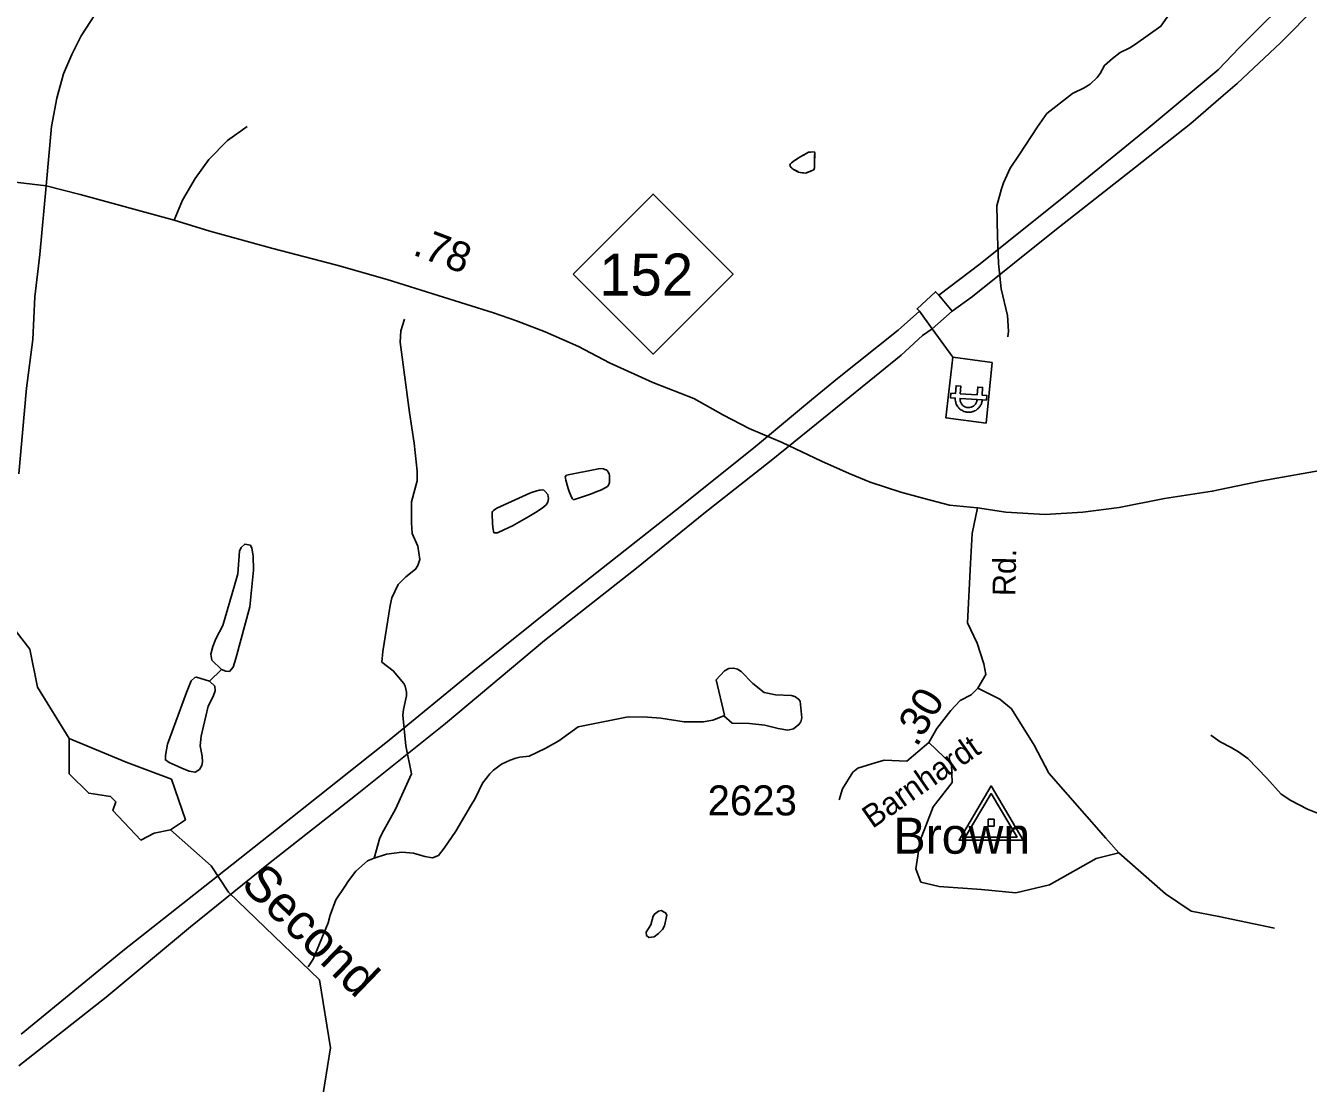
# Model space of a CAD drawing. Extents: x 1473865 to 1648260, y 639067 to 773536.
# Drawn here: x 1559198 to 1564537, y 655168 to 659571 of the extents above; entities that cross this region are included whole.
import ezdxf

# ---------------------------------------------------------------- set-up
doc = ezdxf.new("R2010")
doc.units = 0
for name, color, linetype in [('Exist Hydrographic Creek Single Shore', 7, 'Continuous'), ('Exist Hydrographic Creek Single Shore Label', 7, 'Continuous'), ('Exist Hydrographic Misc Water Feature', 7, 'Continuous'), ('Exist Road Non-System Type 51', 7, 'Continuous'), ('Exist Road Primary NC Attributed', 7, 'Continuous'), ('Exist Road Primary NC Service Mileage Hundredths English Label', 7, 'Continuous'), ('Exist Road Primary NC Shield CELL', 7, 'Continuous'), ('Exist Road Primary NC Shield Number Label', 7, 'Continuous'), ('Exist Road Secondary Mileage Hundredths English Label', 7, 'Continuous'), ('Exist Road Secondary Type 51 Attributed', 7, 'Continuous'), ('Exist Road Secondary Type 51 Label', 7, 'Continuous'), ('Exist Road Secondary Type 51 Number Label', 7, 'Continuous'), ('Exist Survey Geodetic Marker CELL', 7, 'Continuous'), ('Exist Survey Geodetic Marker Label', 7, 'Continuous'), ('Exist Utilities Electrical Power Substation CELL', 7, 'Continuous'), ('Exist Utilities Electrical Transmission Line', 7, 'Continuous')]:
    doc.layers.add(name, color=color, linetype=linetype)

msp = doc.modelspace()

# ---------------------------------------------------------------- linework, layer by layer
at = {"layer": 'Exist Hydrographic Creek Single Shore'}
msp.add_lwpolyline([(1560429.2, 655083), (1560466.2, 655315.3), (1560420.2, 655598.5), (1560042.2, 655963.9), (1559969.2, 656073.7), (1559800.9, 656222.4), (1559862.6, 656264.7), (1559804.2, 656433.7), (1559616.2, 656504.2), (1559378.7, 656602.7), (1559246.3, 656817), (1559215.2, 656975.2), (1559010.3, 657238.6)], dxfattribs=at)
at = {"layer": 'Exist Hydrographic Misc Water Feature'}
msp.add_line((1559962.9, 656841.7), (1560013.1, 656890.8), dxfattribs=at)
for points in [[(1563959.4, 659619.6), (1563922.8, 659568.1), (1563817.9, 659493.3), (1563793.7, 659477.6), (1563753.5, 659458.1), (1563721.2, 659434.4), (1563688.8, 659404.8), (1563670.5, 659371), (1563658.3, 659355.1), (1563628, 659327.5), (1563603.8, 659311.8), (1563555.6, 659288.3), (1563448.9, 659204.6), (1563410, 659150), (1563332.7, 659032.9), (1563296, 658977.3), (1563267.4, 658915.6), (1563259.1, 658891.8), (1563240.3, 658819.9), (1563243.3, 658694.3), (1563247.6, 658579.9), (1563258.4, 658475.7), (1563285.2, 658363.4), (1563288.5, 658299.4), (1563286.2, 658275.4)], [(1562478.7, 658971), (1562470.9, 658967.5), (1562467.8, 658965.8), (1562463.3, 658963.7), (1562457.6, 658962.6), (1562453.6, 658960.8), (1562448.1, 658958.1), (1562445.1, 658956.4), (1562435.6, 658957.7), (1562430.6, 658957.2), (1562421.9, 658959.3), (1562414.4, 658960.8), (1562411.3, 658962.8), (1562406.4, 658966.8), (1562397.9, 658969.7), (1562393.8, 658971.9), (1562387.2, 658976.8), (1562384, 658979.7), (1562379.5, 658985.2), (1562379, 658989.5), (1562380, 658994.6), (1562385.6, 658999.7), (1562391.3, 659003.8), (1562397.8, 659009.3), (1562403.2, 659011.6), (1562409, 659016.2), (1562413.2, 659019.4), (1562417.2, 659021.9), (1562421.6, 659024.2), (1562427.6, 659027.2), (1562431.2, 659029.4), (1562438.7, 659031.9), (1562442.7, 659036.2), (1562455.5, 659043.5), (1562459.7, 659043.6), (1562464.8, 659044.2), (1562473.3, 659045.1), (1562481.6, 659044), (1562482.1, 659040.6), (1562480.9, 659029.9), (1562481.2, 659023.4), (1562481, 659012.3), (1562481, 659007.4), (1562481.1, 659001.1), (1562481.8, 658995.7), (1562481.7, 658989.9), (1562481.5, 658984.4), (1562481.4, 658979.3), (1562478.7, 658971)], [(1562478.7, 658971), (1562470.9, 658967.5), (1562445.1, 658956.4), (1562430.6, 658957.2), (1562414.4, 658960.8), (1562393.8, 658971.9), (1562387.2, 658976.8), (1562384, 658979.7), (1562379.5, 658985.2), (1562379, 658989.5), (1562380, 658994.6), (1562385.6, 658999.7), (1562397.8, 659009.3), (1562413.2, 659019.4), (1562417.2, 659021.9), (1562455.5, 659043.5), (1562473.3, 659045.1), (1562481.6, 659044), (1562482.1, 659040.6), (1562481.8, 658995.7), (1562481.7, 658989.9), (1562481.4, 658979.3), (1562478.7, 658971)], [(1560648.1, 656105.7), (1560672.1, 656189.6), (1560688.5, 656221.4), (1560737.5, 656308.9), (1560803.1, 656456.1), (1560780.4, 656572.4), (1560767.9, 656700.6), (1560770.1, 656724.5), (1560782.7, 656780.4), (1560782.9, 656796.4), (1560777.2, 656820.5), (1560771.3, 656832.5), (1560727.9, 656885), (1560680.2, 656921.6), (1560683.7, 656965.3), (1560714.9, 657157.2), (1560721.2, 657189.2), (1560747.9, 657244.8), (1560780.2, 657276.5), (1560820.6, 657308), (1560830.7, 657323.9), (1560839, 657347.8), (1560829.7, 657403.9), (1560806.2, 657456.2), (1560803, 657501.3), (1560803.7, 657588.2), (1560826.6, 657676), (1560827.1, 657715.9), (1560814.4, 657832.1), (1560795.8, 657960.4), (1560757, 658252.8), (1560759.6, 658300.8), (1560774.1, 658348.6)], [(1561477.6, 657597.4), (1561473.4, 657600.8), (1561469.7, 657608.4), (1561460.4, 657630.9), (1561456.3, 657643.3), (1561445.8, 657678.1), (1561444, 657687.6), (1561443.6, 657692.9), (1561449, 657699), (1561581.4, 657726.2), (1561595.7, 657726.5), (1561602.3, 657725.5), (1561608.5, 657723.5), (1561614.6, 657721.5), (1561619.4, 657717.7), (1561622.1, 657712.4), (1561625.8, 657705.2), (1561627.7, 657697.6), (1561628.4, 657682.4), (1561627.4, 657669.5), (1561624.3, 657658.2), (1561619, 657652.1), (1561594.5, 657638.6), (1561583.6, 657634), (1561544.4, 657618.8), (1561527.3, 657613.4), (1561477.6, 657597.4)], [(1561140.3, 657547.5), (1561139.8, 657544.3), (1561139.6, 657526.8), (1561140.5, 657510), (1561141.1, 657499.4), (1561142.3, 657482.2), (1561146.8, 657459.5), (1561161.4, 657459.7), (1561187.8, 657471.4), (1561224.1, 657488.8), (1561291.8, 657527.7), (1561320.5, 657544.5), (1561346.9, 657561.6), (1561364.7, 657576.3), (1561371.3, 657587.2), (1561373.7, 657601.8), (1561371, 657619.3), (1561360.3, 657631.5), (1561355.1, 657636.7), (1561348.7, 657638.6), (1561339.5, 657637.2), (1561335.2, 657636.6), (1561324.9, 657634.5), (1561303.3, 657627.2), (1561296.3, 657624.3), (1561158.6, 657562.3), (1561154.2, 657559.4), (1561144.7, 657551.8), (1561140.3, 657547.5)], [(1560013.1, 656890.8), (1560031.5, 656883.1), (1560045.8, 656882.8), (1560061.8, 656900.8), (1560072.2, 656936.7), (1560130.6, 657152), (1560146.3, 657303.8), (1560144.9, 657363.9), (1560139.3, 657396), (1560133.4, 657408), (1560109.5, 657412.3), (1560095.3, 657398.5), (1560087.1, 657382.5), (1560080.1, 657288.6), (1560067.5, 657240.7), (1560017.7, 657073.3), (1559989.1, 657017.6), (1559976.7, 656985.8), (1559968.4, 656953.9), (1559972.1, 656929.8), (1560013.1, 656890.8)], [(1562103.2, 656698.1), (1562106.4, 656701), (1562072, 656847.4), (1562106.4, 656885), (1562124.5, 656894.8), (1562144.5, 656896.5), (1562160.5, 656892.3), (1562176.4, 656882.1), (1562223.8, 656831.6), (1562271.4, 656795), (1562319.4, 656784.5), (1562383.4, 656781.8), (1562399.3, 656777.6), (1562415.2, 656767.4), (1562421.1, 656759.3), (1562428.4, 656689.2), (1562424.2, 656673.2), (1562416.1, 656661.4), (1562393.8, 656643.6), (1562369.7, 656637.9), (1562329.9, 656644.4), (1562274, 656659), (1562210, 656665.8), (1562138, 656666.6), (1562103.2, 656698.1)], [(1559833.1, 656487.4), (1559795.3, 656503.9), (1559779.4, 656514), (1559779.6, 656532), (1559788.1, 656579.9), (1559866.6, 656795), (1559887.1, 656842.8), (1559901.2, 656856.7), (1559909.2, 656858.6), (1559962.9, 656841.7)], [(1559962.9, 656841.7), (1559984.9, 656821.7), (1559986.6, 656801.7), (1559978.4, 656777.8), (1559957.9, 656738), (1559928.6, 656612.3), (1559924.1, 656572.4), (1559931.7, 656530.3), (1559933.4, 656506.2), (1559931.2, 656490.3), (1559921, 656474.4), (1559902.9, 656462.6), (1559878.9, 656466.9), (1559847.1, 656479.3), (1559833.1, 656487.4)], [(1560648.1, 656105.7), (1560699.4, 656121.3), (1560763.6, 656130.5), (1560811.4, 656126), (1560859.3, 656111.5), (1560891.3, 656107), (1560915.4, 656116.8), (1560939.8, 656146.5), (1560988.6, 656217.9), (1561049.7, 656321.2), (1561068.1, 656353), (1561098.8, 656416.7), (1561129.3, 656456.3), (1561145.5, 656472.1), (1561177.8, 656495.8), (1561214, 656513.4), (1561238.1, 656521), (1561254.1, 656524.9), (1561294.1, 656530.4), (1561360.6, 656561.6), (1561416.9, 656593), (1561497.6, 656652.1), (1561706.1, 656693.7), (1561786.2, 656692.7), (1561842.1, 656688.1), (1561938, 656672.9), (1562018, 656672), (1562058.1, 656679.6), (1562103.2, 656698.1)], [(1564574.8, 656292.2), (1564532.9, 656308.7), (1564463.3, 656345.5), (1564423.5, 656372), (1564364.3, 656438.7), (1564285.1, 656519.6), (1564245.5, 656548.1), (1564215.6, 656566.4), (1564169.9, 656588.9), (1564130.2, 656617.4)], [(1559378.7, 656602.7), (1559378.7, 656456.4), (1559459.9, 656375.2), (1559550.9, 656362.2), (1559573.6, 656339.4), (1559560.6, 656303.7), (1559677.5, 656180.1), (1559732.7, 656209.4), (1559800.9, 656222.4)], [(1560374.1, 655653.1), (1560394.5, 655684.8), (1560456.2, 655836.1), (1560464.5, 655868), (1560489.2, 655931.7), (1560525.8, 655987.3), (1560542.1, 656011.1), (1560572.6, 656050.8), (1560621.1, 656094.2), (1560648.1, 656105.7)], [(1561799.5, 655827.2), (1561809, 655864.4), (1561815.1, 655872.3), (1561831.2, 655884.1), (1561843.3, 655888), (1561861.1, 655877.7), (1561867.1, 655867.7), (1561856.6, 655823.8), (1561848.4, 655807.9), (1561832.2, 655792.1), (1561814.1, 655778.3), (1561792, 655774.6), (1561782.1, 655782.7), (1561780.2, 655796.7), (1561799.5, 655827.2)]]:
    msp.add_lwpolyline(points, dxfattribs=at)
at = {"layer": 'Exist Road Non-System Type 51'}
for points in [[(1559815.3, 658761.1), (1559850.4, 658844.7), (1559903.4, 658934), (1559960.5, 659013.3), (1560037.5, 659092.2), (1560120.3, 659151.2)], [(1563161, 656812.4), (1563252.2, 656766.7), (1563300.9, 656727.2), (1563395.2, 656575), (1563456, 656459.3), (1563693.2, 656188.5), (1563747.9, 656127.6)], [(1562957.2, 656587.2), (1563051.5, 656495.9), (1563054.5, 656419.8), (1562975.5, 656319.3), (1562920.7, 656179.3), (1562902.5, 656060.6), (1562923.8, 656005.9), (1562999.8, 655987.6), (1563176.2, 655975.4), (1563319.1, 655960.2), (1563459, 655993.7), (1563653.7, 656103.3), (1563747.9, 656127.6)], [(1563747.9, 656127.6), (1563942.6, 655957.2), (1564049, 655884.1), (1564164.6, 655862.8), (1564395.7, 655814.1)]]:
    msp.add_lwpolyline(points, dxfattribs=at)
at = {"layer": 'Exist Road Primary NC Attributed'}
for points in [[(1557994.8, 659046.5), (1558699.5, 658973.8), (1559282.9, 658904.1)], [(1559282.9, 658904.1), (1559424.5, 658868.3), (1559815.3, 658761.1), (1559964.8, 658715.1), (1560225.9, 658643.6), (1560493.2, 658574.2), (1560702.5, 658513.3), (1560914.1, 658447.8), (1561144.9, 658375.5), (1561240.5, 658342.4), (1561360, 658296.7), (1561499.2, 658234.9), (1561628.5, 658167.2), (1561807.6, 658084.8), (1561978.7, 658018.4), (1562102, 657949), (1562209.3, 657893.4), (1562346.6, 657835.6), (1562509.7, 657757.5), (1562625.1, 657705.9), (1562712.6, 657670.7), (1562840.2, 657629.1), (1562937.9, 657601.7), (1563043.6, 657574.4), (1563159.4, 657562.9)], [(1563159.4, 657562.9), (1563277.3, 657545.5), (1563441.2, 657535.2), (1563597.5, 657545.2), (1563749.8, 657565.1), (1563938.4, 657602.7), (1564136.7, 657632.2), (1564343.5, 657675.6), (1564624.2, 657726), (1564828.6, 657759.3), (1565247.8, 657837.8), (1565420.2, 657863.6), (1565550.4, 657881.9), (1565692.8, 657898.1), (1565994.8, 657900), (1566124.6, 657880.4), (1566308.5, 657858), (1566535.9, 657807), (1566725.3, 657752.6), (1566936.4, 657713.8), (1567249.9, 657621.5), (1567427.2, 657573.3), (1567724.6, 657503.3), (1567930.6, 657451.1)]]:
    msp.add_lwpolyline(points, dxfattribs=at)
at = {"layer": 'Exist Road Primary NC Shield CELL'}
msp.add_lwpolyline([(1561476, 658536.6), (1561809, 658869.6), (1562142, 658536.6), (1561809, 658203.6)], close=True, dxfattribs=at)
at = {"layer": 'Exist Road Secondary Type 51 Attributed'}
for points in [[(1560953.2, 661413.2), (1560888.9, 661240), (1560820, 661022.9), (1560793.1, 660937.2), (1560735.1, 660787.9), (1560618.9, 660615.4), (1560537.8, 660520.4), (1560446.5, 660431.6), (1559957.5, 660043.7), (1559751.9, 659908), (1559693.2, 659854.8), (1559486, 659615.8), (1559428.8, 659528.5), (1559389.8, 659450.8), (1559354.8, 659369.3), (1559327.1, 659269.2), (1559305.3, 659151), (1559282.9, 658904.1)], [(1559282.9, 658904.1), (1559257.3, 658618.3), (1559236, 658442.2), (1559226.8, 658264.6), (1559201.4, 658061.8), (1559169.2, 657705.6)], [(1563159.4, 657562.9), (1563138.1, 657457.2), (1563130.7, 657331.7), (1563118.5, 657085.2), (1563158.1, 656999.9), (1563185.4, 656914.2), (1563194.6, 656869.1), (1563161, 656812.4), (1563133.7, 656785), (1563087.4, 656761.5), (1563049, 656720.1), (1562990.7, 656645), (1562957.2, 656587.2), (1562866, 656509.4), (1562771.8, 656513), (1562719.2, 656498.4), (1562661, 656479.2), (1562640.7, 656462.7), (1562597.8, 656393.4), (1562584.1, 656347.7)]]:
    msp.add_lwpolyline(points, dxfattribs=at)
at = {"layer": 'Exist Survey Geodetic Marker CELL'}
for points in [[(1563350.1, 656179.9), (1563216.2, 656405.9), (1563082.7, 656179.9)], [(1563324.2, 656192), (1563108.7, 656192), (1563216.2, 656374.1)], [(1563228.5, 656238.6), (1563228.5, 656266.8), (1563204.2, 656266.8), (1563204.2, 656238.6)]]:
    msp.add_lwpolyline(points, close=True, dxfattribs=at)
at = {"layer": 'Exist Utilities Electrical Power Substation CELL'}
msp.add_lwpolyline([(1563048.8, 658040.7), (1563068.3, 658039.5), (1563070.3, 658071.6), (1563090.1, 658070.4), (1563088.1, 658038.3), (1563158.8, 658033.8), (1563160.8, 658065.9), (1563180.6, 658064.7), (1563178.6, 658032.6), (1563198.1, 658031.3), (1563196.8, 658011.9), (1563177.3, 658013.2), (1563157.6, 658014.4), (1563086.9, 658018.9), (1563087.1, 658012.7), (1563088, 658007.3), (1563090.1, 658001.5), (1563093.4, 657995.9), (1563097.8, 657990.8), (1563100.3, 657988.6), (1563103.2, 657986.8), (1563106.9, 657984.5), (1563111, 657982.9), (1563115.6, 657981.6), (1563119.3, 657981.1), (1563123.5, 657981), (1563128.2, 657981.4), (1563132.6, 657982.4), (1563135.6, 657983.4), (1563139, 657985), (1563142.6, 657987.2), (1563145.9, 657989.7), (1563148.8, 657992.5), (1563151.1, 657995.3), (1563152.5, 657997.6), (1563154.1, 658000.2), (1563155.7, 658003.7), (1563156.3, 658005.9), (1563157.4, 658009.5), (1563157.8, 658012.3), (1563158, 658014.4), (1563179.6, 658013), (1563179.1, 658009.6), (1563178.5, 658007), (1563177.8, 658003.7), (1563176.8, 658000.4), (1563175.6, 657996.7), (1563174.3, 657993.7), (1563172.8, 657990.6), (1563170.7, 657987.2), (1563168.2, 657983.7), (1563165.5, 657980.3), (1563162.7, 657977.4), (1563159.9, 657974.9), (1563156.1, 657971.9), (1563152.1, 657969.2), (1563147.8, 657967), (1563143.2, 657965), (1563139.8, 657963.8), (1563136.6, 657963), (1563133.4, 657962.3), (1563129.6, 657961.7), (1563125.8, 657961.5), (1563122.4, 657961.4), (1563118, 657961.6), (1563115, 657962), (1563111.6, 657962.6), (1563108.1, 657963.6), (1563103.3, 657965), (1563098.4, 657967.2), (1563094.1, 657969.5), (1563090.7, 657971.8), (1563086.7, 657974.8), (1563083.7, 657977.6), (1563081.9, 657979.3), (1563079.6, 657982), (1563077.8, 657984.3), (1563075.3, 657987.8), (1563072.9, 657992.2), (1563071.2, 657996), (1563069.8, 657999.5), (1563068.9, 658002.7), (1563067.6, 658008), (1563067.1, 658012.4), (1563066.9, 658016.2), (1563066.8, 658020.1), (1563047.6, 658021.3)], close=True, dxfattribs=at)
at = {"layer": 'Exist Utilities Electrical Transmission Line'}
for p, q in [((1562999.1, 658448.7), (1563054.3, 658382.2)), ((1562971.4, 658309), (1562918.3, 658381.7)), ((1563054.3, 658382.2), (1562971.4, 658309)), ((1562971.4, 658309), (1563056.3, 658190))]:
    msp.add_line(p, q, dxfattribs=at)
for points in [[(1563054.3, 658382.2), (1563139, 658443.3), (1563482.1, 658717.5), (1563817, 658981.9), (1564047, 659163.3), (1564172.2, 659271.8), (1564240.8, 659329.1), (1564420.7, 659499.1), (1564728.2, 659809.9)], [(1564499.2, 659728.5), (1564250.5, 659479.2), (1564161.3, 659386.1), (1563870.7, 659143.3), (1563525.7, 658863.1), (1563170.4, 658578.9), (1562999.1, 658448.7)], [(1562918.3, 658381.7), (1562908.3, 658391.7), (1562985.1, 658463), (1562999.1, 658448.7)], [(1562918.3, 658381.7), (1562829.4, 658302.7), (1562577.1, 658101.5), (1562468.2, 658012.6), (1562227.8, 657811.2), (1561903.1, 657552.8), (1561430.9, 657180), (1561059.5, 656881.9), (1560710.4, 656595.8), (1560335, 656297.9), (1559996, 656029.6), (1559602.6, 655720), (1559178.8, 655372.6)], [(1559169.5, 655240.7), (1559532.6, 655526.7), (1559883.9, 655818.9), (1560208.7, 656081.3), (1560569.9, 656365.4), (1560945.3, 656665.3), (1561357.1, 657010.8), (1561740.3, 657312.6), (1562020.8, 657539.4), (1562301.4, 657760.5), (1562489, 657912.4), (1562709.1, 658090), (1562842.3, 658198.6), (1562931.3, 658281.4), (1562971.4, 658309)], [(1563056.3, 658190), (1563220.1, 658168.3), (1563195.4, 657916.5), (1563027.6, 657938.3), (1563056.3, 658190)]]:
    msp.add_lwpolyline(points, dxfattribs=at)

# ---------------------------------------------------------------- texts
at = {"layer": 'Exist Hydrographic Creek Single Shore Label'}
msp.add_text('Second', height=150, rotation=315.9718, dxfattribs=at).set_placement((1560088.1, 655989.5))
at = {"layer": 'Exist Road Primary NC Service Mileage Hundredths English Label'}
msp.add_text('.78', height=125, rotation=339.1052, dxfattribs=at).set_placement((1560804.3, 658618.7))
at = {"layer": 'Exist Road Primary NC Shield Number Label'}
msp.add_text('152', height=175, dxfattribs=at).set_placement((1561585.2, 658446.9))
at = {"layer": 'Exist Road Secondary Mileage Hundredths English Label'}
msp.add_text('.30', height=125, rotation=59.2199, dxfattribs=at).set_placement((1562907, 656564.3))
at = {"layer": 'Exist Road Secondary Type 51 Label'}
for s, rotation, p in [('Rd.', 88.8422, (1563317, 657195.1)), ('Barnhardt', 34.8775, (1562722.6, 656226.1))]:
    msp.add_text(s, height=95, rotation=rotation, dxfattribs=at).set_placement(p)
at = {"layer": 'Exist Road Secondary Type 51 Number Label'}
msp.add_text('2623', height=125, dxfattribs=at).set_placement((1562036.2, 656283.1))
at = {"layer": 'Exist Survey Geodetic Marker Label'}
msp.add_text('Brown', height=150, dxfattribs=at).set_placement((1562810.1, 656123.7))

doc.saveas('drawing.dxf')
